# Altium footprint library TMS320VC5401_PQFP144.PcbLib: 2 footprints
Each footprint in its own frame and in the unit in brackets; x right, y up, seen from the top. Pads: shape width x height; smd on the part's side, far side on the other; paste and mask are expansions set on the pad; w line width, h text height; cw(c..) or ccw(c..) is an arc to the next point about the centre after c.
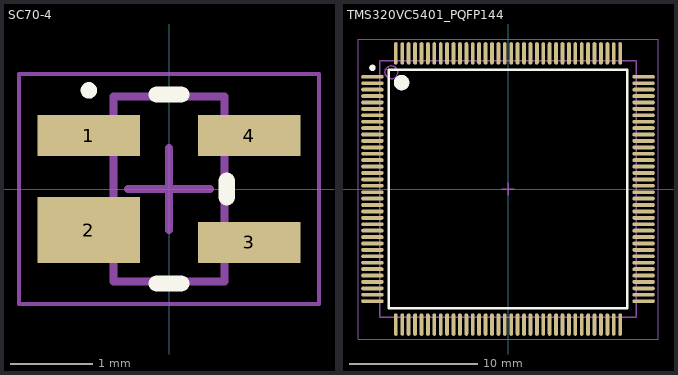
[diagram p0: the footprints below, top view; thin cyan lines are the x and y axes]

## SC70-4 [mm] "SOT143, 4-Leads, Body 2.03x2.10mm, Pitch 1.30mm, IPC Medium Density"
height 1.1
pads (4):
  rect 1.25x0.5 smd: 1(-0.975,0.65) 3(0.975,-0.65) 4(0.975,0.65)
  rect 1.25x0.8 smd: 2(-0.975,-0.5)
Top Overlay:
  circle w0.1: c-0.975,1.2 r0.05
  lines w0.2: -0.15,-1.15 0.15,-1.15 ; -0.15,1.15 0.15,1.15 ; 0.7,-0.1 0.7,0.1
Mechanical 13:
  lines w0.1: -0.675,-1.125 0.675,-1.125 0.675,1.125 -0.675,1.125 -0.675,-1.125
Mechanical 15:
  lines w0.05: -1.825,-1.4 1.825,-1.4 1.825,1.4 -1.825,1.4 -1.825,-1.4
  lines w0.1: -0.5,0 0.5,0 ; 0,-0.5 0,0.5
3D body: height 1.1, standoff 0, extent -0.675,-1.125 0.675,1.125

## TMS320VC5401_PQFP144 [mm] "TSQFP, 144-Leads, Body 20.00x20.00mm, Pitch 0.50mm, IPC Medium Density"
height 1.6
pads (144):
  oval 1.75x0.3 smd: 1(-10.575,8.75) 2(-10.575,8.25) 3(-10.575,7.75) 4(-10.575,7.25) 5(-10.575,6.75) 6(-10.575,6.25) 7(-10.575,5.75) 8(-10.575,5.25) 9(-10.575,4.75) 10(-10.575,4.25) 11(-10.575,3.75) 12(-10.575,3.25) 13(-10.575,2.75) 14(-10.575,2.25) 15(-10.575,1.75) 16(-10.575,1.25) 17(-10.575,0.75) 18(-10.575,0.25) 19(-10.575,-0.25) 20(-10.575,-0.75) 21(-10.575,-1.25) 22(-10.575,-1.75) 23(-10.575,-2.25) 24(-10.575,-2.75) 25(-10.575,-3.25) 26(-10.575,-3.75) 27(-10.575,-4.25) 28(-10.575,-4.75) 29(-10.575,-5.25) 30(-10.575,-5.75) 31(-10.575,-6.25) 32(-10.575,-6.75) 33(-10.575,-7.25) 34(-10.575,-7.75) 35(-10.575,-8.25) 36(-10.575,-8.75) 73(10.575,-8.75) 74(10.575,-8.25) 75(10.575,-7.75) 76(10.575,-7.25) 77(10.575,-6.75) 78(10.575,-6.25) 79(10.575,-5.75) 80(10.575,-5.25) 81(10.575,-4.75) 82(10.575,-4.25) 83(10.575,-3.75) 84(10.575,-3.25) 85(10.575,-2.75) 86(10.575,-2.25) 87(10.575,-1.75) 88(10.575,-1.25) 89(10.575,-0.75) 90(10.575,-0.25) 91(10.575,0.25) 92(10.575,0.75) 93(10.575,1.25) 94(10.575,1.75) 95(10.575,2.25) 96(10.575,2.75) 97(10.575,3.25) 98(10.575,3.75) 99(10.575,4.25) 100(10.575,4.75) 101(10.575,5.25) 102(10.575,5.75) 103(10.575,6.25) 104(10.575,6.75) 105(10.575,7.25) 106(10.575,7.75) 107(10.575,8.25) 108(10.575,8.75)
  oval 0.3x1.75 smd: 37(-8.75,-10.575) 38(-8.25,-10.575) 39(-7.75,-10.575) 40(-7.25,-10.575) 41(-6.75,-10.575) 42(-6.25,-10.575) 43(-5.75,-10.575) 44(-5.25,-10.575) 45(-4.75,-10.575) 46(-4.25,-10.575) 47(-3.75,-10.575) 48(-3.25,-10.575) 49(-2.75,-10.575) 50(-2.25,-10.575) 51(-1.75,-10.575) 52(-1.25,-10.575) 53(-0.75,-10.575) 54(-0.25,-10.575) 55(0.25,-10.575) 56(0.75,-10.575) 57(1.25,-10.575) 58(1.75,-10.575) 59(2.25,-10.575) 60(2.75,-10.575) 61(3.25,-10.575) 62(3.75,-10.575) 63(4.25,-10.575) 64(4.75,-10.575) 65(5.25,-10.575) 66(5.75,-10.575) 67(6.25,-10.575) 68(6.75,-10.575) 69(7.25,-10.575) 70(7.75,-10.575) 71(8.25,-10.575) 72(8.75,-10.575) 109(8.75,10.575) 110(8.25,10.575) 111(7.75,10.575) 112(7.25,10.575) 113(6.75,10.575) 114(6.25,10.575) 115(5.75,10.575) 116(5.25,10.575) 117(4.75,10.575) 118(4.25,10.575) 119(3.75,10.575) 120(3.25,10.575) 121(2.75,10.575) 122(2.25,10.575) 123(1.75,10.575) 124(1.25,10.575) 125(0.75,10.575) 126(0.25,10.575) 127(-0.25,10.575) 128(-0.75,10.575) 129(-1.25,10.575) 130(-1.75,10.575) 131(-2.25,10.575) 132(-2.75,10.575) 133(-3.25,10.575) 134(-3.75,10.575) 135(-4.25,10.575) 136(-4.75,10.575) 137(-5.25,10.575) 138(-5.75,10.575) 139(-6.25,10.575) 140(-6.75,10.575) 141(-7.25,10.575) 142(-7.75,10.575) 143(-8.25,10.575) 144(-8.75,10.575)
Top Overlay:
  circle w0.6: c-8.3,8.3 r0.3
  circle w0.25: c-10.575,9.45 r0.125
  lines w0.2: -9.3,-9.3 9.3,-9.3 9.3,9.3 -9.3,9.3 -9.3,-9.3
Mechanical 13:
  circle w0.1: c-9.1,9.1 r0.5
  lines w0.1: -10,-10 10,-10 10,10 -10,10 -10,-10
Mechanical 15:
  lines w0.05: -11.7,-11.7 11.7,-11.7 11.7,11.7 -11.7,11.7 -11.7,-11.7
  lines w0.1: -0.5,0 0.5,0 ; 0,-0.5 0,0.5
3D body: height 1.6, standoff 0.25, extent -10,-10 10,10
